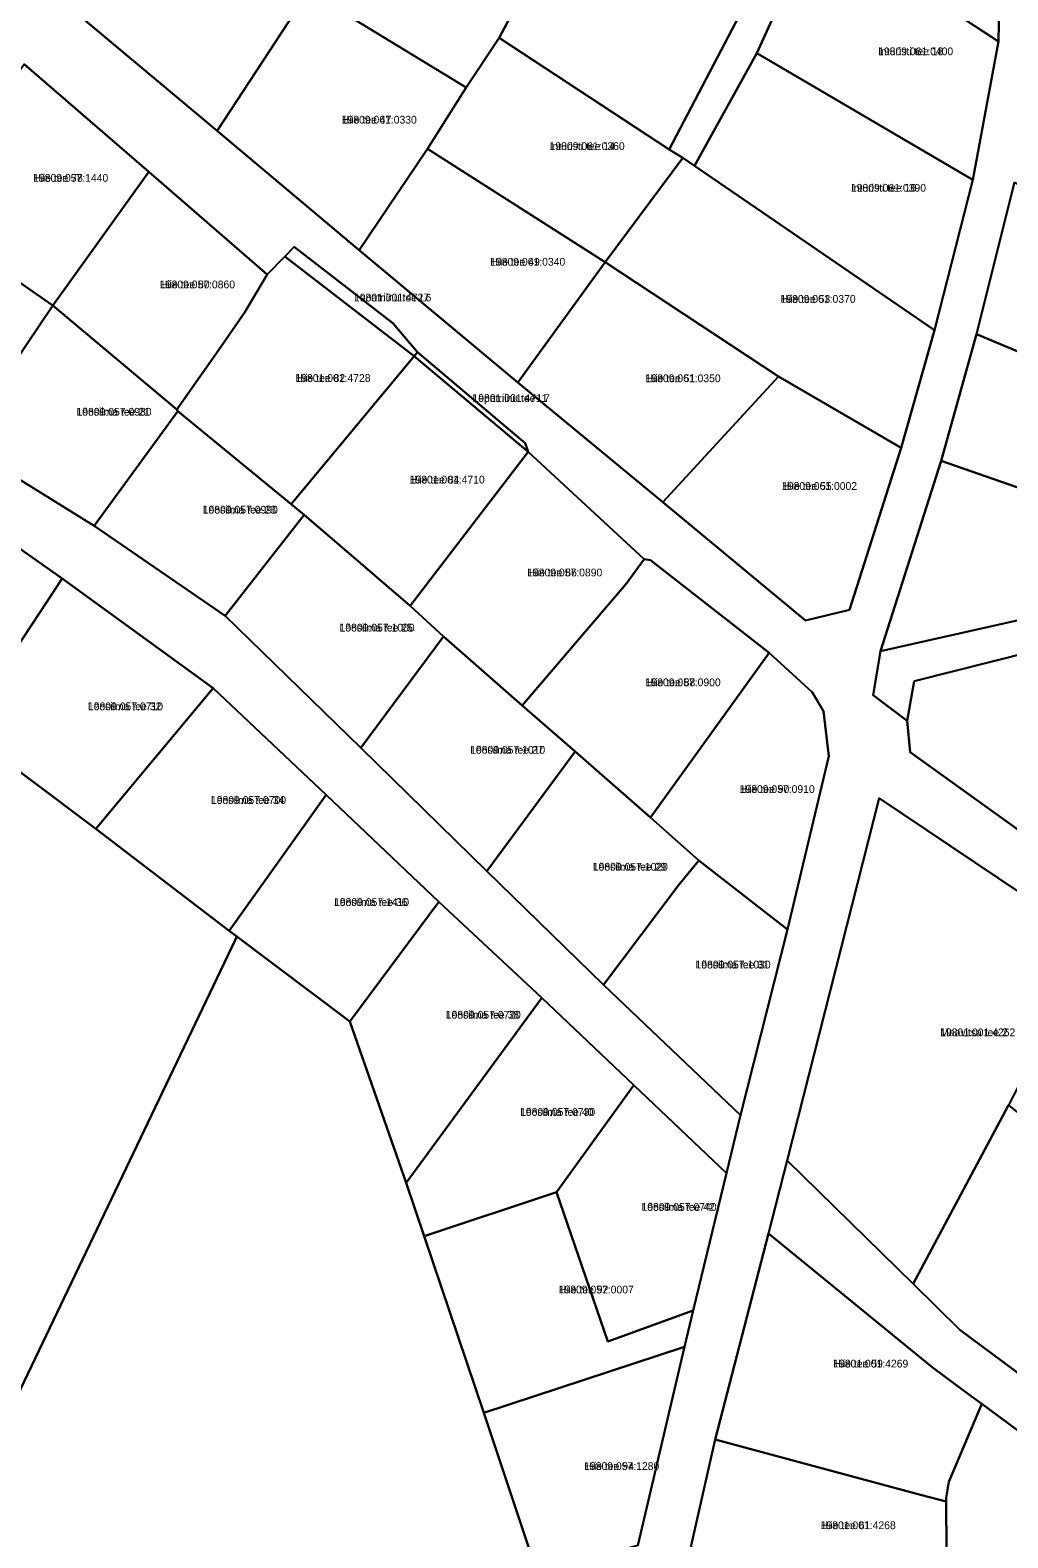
# Model space of a CAD drawing. Extents: x 516875 to 535633, y 6574491 to 6593094.
# Drawn here: x 522140.5 to 522329.4, y 6587201.6 to 6587492.9 of the extents above; entities that cross this region are included whole.
import ezdxf

# ---------------------------------------------------------------- set-up
doc = ezdxf.new("R2010")
doc.units = 0
for name, color, linetype in [('L_AADRESS', 7, 'Continuous'), ('PIIR', 7, 'Continuous'), ('TUNNUS', 7, 'Continuous')]:
    doc.layers.add(name, color=color, linetype=linetype)

msp = doc.modelspace()

# ---------------------------------------------------------------- linework, layer by layer
at = {"layer": 'PIIR'}
for points in [[(522130.99, 6587511.59), (522148.76, 6587496.75), (522176.64, 6587473.46), (522204.05, 6587450.37), (522234.69, 6587424.83), (522262.73, 6587401.7), (522290.24, 6587378.83), (522298.74, 6587380.89), (522308.74, 6587412.2), (522315.2, 6587434.91), (522322.58, 6587463.94), (522327.53, 6587490.67), (522327.74, 6587501.22), (522336.67, 6587532.97), (522349.11, 6587575.14), (522323.48, 6587593.16), (522303.51, 6587607.38), (522280.12, 6587625.51), (522255.95, 6587641.89), (522232.81, 6587658.84), (522211.04, 6587675.41), (522190.18, 6587691.24), (522170.33, 6587706.74), (522137.56, 6587733.11)], [(522291.63, 6587512.13), (522280.86, 6587488.44), (522268.8, 6587466.65), (522266.59, 6587468.22), (522263.91, 6587469.85), (522284.58, 6587509.35)], [(522327.74, 6587501.22), (522327.53, 6587490.67), (522295.68, 6587511.57)], [(522257.9, 6587200.12), (522266.88, 6587238.51), (522268.58, 6587245.55), (522275, 6587272.07), (522277.69, 6587283.26), (522286.81, 6587319.14), (522294.76, 6587352.61), (522293.75, 6587361.34), (522291.58, 6587364.97), (522283.22, 6587372.57), (522260.3, 6587390.51), (522259.13, 6587390.71), (522236.72, 6587411.45), (522236.12, 6587413.08), (522215.32, 6587430.67), (522210.59, 6587436.27), (522191.52, 6587451.05), (522189.67, 6587449.18), (522186.26, 6587445.71), (522163.43, 6587465.52), (522139.37, 6587486.34)], [(522330.66, 6587463.51), (522323.28, 6587434.15), (522316.46, 6587409.68), (522304.78, 6587372.9), (522303.37, 6587364.42), (522309.93, 6587359.42), (522310.5, 6587353.43), (522345.95, 6587327.88)], [(522126.96, 6587413.14), (522152.9, 6587397.13), (522178.19, 6587379.72), (522204.4, 6587354.21), (522228.72, 6587330.44), (522251.25, 6587308.48), (522277.69, 6587283.26), (522275, 6587272.07), (522257.13, 6587289.06), (522239.31, 6587305.92), (522219.44, 6587324.5), (522197.69, 6587345.18), (522175.86, 6587365.75), (522146.69, 6587386.92), (522120.03, 6587405.7)], [(522333.74, 6587372.78), (522311.25, 6587367.11), (522309.93, 6587359.42), (522303.37, 6587364.42), (522304.78, 6587372.9), (522332, 6587379)], [(522345.86, 6587316.74), (522304.47, 6587344.54), (522286.72, 6587274.54), (522283.12, 6587260.43), (522272.83, 6587220.63), (522268.21, 6587200.15)], [(522358.65, 6587201.13), (522335.3, 6587219.37), (522327.57, 6587225.1), (522324.3, 6587227.5), (522322.3, 6587229), (522314.73, 6587234.58), (522283.12, 6587260.43), (522286.72, 6587274.54), (522311.09, 6587250.66), (522320.1, 6587241.82), (522330.58, 6587234.01), (522347.44, 6587220.78), (522356.18, 6587214.07), (522375.8, 6587198.81)]]:
    msp.add_lwpolyline(points, dxfattribs=at)
for points in [[(522231.08, 6587491.41), (522224.74, 6587481.79), (522194.26, 6587500.4), (522211.52, 6587527.95), (522223.62, 6587525.51), (522245.69, 6587518.92)], [(522176.64, 6587473.46), (522148.76, 6587496.75), (522164.77, 6587519.53), (522194.26, 6587500.4)], [(522263.91, 6587469.85), (522231.08, 6587491.41), (522245.69, 6587518.92), (522284.58, 6587509.35)], [(522322.58, 6587463.94), (522280.86, 6587488.44), (522291.63, 6587512.13), (522295.68, 6587511.57), (522327.53, 6587490.67)], [(522217.24, 6587469.94), (522204.05, 6587450.37), (522176.64, 6587473.46), (522194.26, 6587500.4), (522224.74, 6587481.79)], [(522251.58, 6587448.05), (522217.24, 6587469.94), (522224.74, 6587481.79), (522231.08, 6587491.41), (522263.91, 6587469.85), (522266.59, 6587468.22)], [(522315.2, 6587434.91), (522268.8, 6587466.65), (522280.86, 6587488.44), (522322.58, 6587463.94)], [(522118.75, 6587457.97), (522139.37, 6587486.34), (522163.43, 6587465.52), (522144.9, 6587439.69), (522119.54, 6587457.3)], [(522234.69, 6587424.83), (522204.05, 6587450.37), (522217.24, 6587469.94), (522251.58, 6587448.05)], [(522308.74, 6587412.2), (522285.04, 6587425.96), (522251.58, 6587448.05), (522266.59, 6587468.22), (522268.8, 6587466.65), (522315.2, 6587434.91)], [(522163.43, 6587465.52), (522186.26, 6587445.71), (522181.95, 6587438.38), (522177.06, 6587431.35), (522168.85, 6587419.63), (522144.9, 6587439.69)], [(522330.66, 6587463.51), (522367.38, 6587436.69), (522363.22, 6587425.93), (522361.09, 6587418.34), (522323.28, 6587434.15)], [(522119.54, 6587457.3), (522144.9, 6587439.69), (522126.96, 6587413.14), (522102.56, 6587430.43)], [(522189.67, 6587449.18), (522191.52, 6587451.05), (522210.59, 6587436.27), (522215.32, 6587430.67), (522214.65, 6587429.9)], [(522186.26, 6587445.71), (522189.67, 6587449.18), (522214.65, 6587429.9), (522190.91, 6587401.28), (522169.02, 6587419.25), (522168.85, 6587419.63), (522177.06, 6587431.35), (522181.95, 6587438.38)], [(522262.73, 6587401.7), (522234.69, 6587424.83), (522251.58, 6587448.05), (522285.04, 6587425.96)], [(522144.9, 6587439.69), (522168.85, 6587419.63), (522169.02, 6587419.25), (522152.9, 6587397.13), (522126.96, 6587413.14)], [(522323.28, 6587434.15), (522361.09, 6587418.34), (522355.52, 6587396.09), (522316.46, 6587409.68)], [(522214.65, 6587429.9), (522215.32, 6587430.67), (522236.12, 6587413.08), (522236.72, 6587411.45)], [(522190.91, 6587401.28), (522214.65, 6587429.9), (522236.72, 6587411.45), (522213.89, 6587381.65), (522193.41, 6587399.22)], [(522308.74, 6587412.2), (522298.74, 6587380.89), (522290.24, 6587378.83), (522262.73, 6587401.7), (522285.04, 6587425.96)], [(522169.02, 6587419.25), (522190.91, 6587401.28), (522193.41, 6587399.22), (522178.19, 6587379.72), (522152.9, 6587397.13)], [(522220.32, 6587375.75), (522213.89, 6587381.65), (522236.72, 6587411.45), (522259.13, 6587390.71), (522255.64, 6587385.92), (522235.57, 6587362.44)], [(522316.46, 6587409.68), (522355.52, 6587396.09), (522350.49, 6587380.66), (522332, 6587379), (522304.78, 6587372.9)], [(522120.03, 6587405.7), (522146.69, 6587386.92), (522127.48, 6587357.83), (522099.49, 6587379.1)], [(522193.41, 6587399.22), (522213.89, 6587381.65), (522220.32, 6587375.75), (522204.4, 6587354.21), (522178.19, 6587379.72)], [(522235.57, 6587362.44), (522255.64, 6587385.92), (522259.13, 6587390.71), (522260.3, 6587390.51), (522283.22, 6587372.57), (522260.34, 6587340.79), (522245.76, 6587353.54)], [(522146.69, 6587386.92), (522175.86, 6587365.75), (522153.17, 6587338.57), (522127.48, 6587357.83)], [(522220.32, 6587375.75), (522235.57, 6587362.44), (522245.76, 6587353.54), (522228.72, 6587330.44), (522204.4, 6587354.21)], [(522309.93, 6587359.42), (522311.25, 6587367.11), (522333.74, 6587372.78), (522364.67, 6587374.82), (522345.95, 6587327.88), (522310.5, 6587353.43)], [(522260.34, 6587340.79), (522283.22, 6587372.57), (522291.58, 6587364.97), (522293.75, 6587361.34), (522294.76, 6587352.61), (522286.81, 6587319.14), (522269.66, 6587332.48)], [(522175.86, 6587365.75), (522197.69, 6587345.18), (522178.96, 6587318.86), (522153.17, 6587338.57)], [(522037.89, 6587203.55), (522127.48, 6587357.83), (522153.17, 6587338.57), (522178.96, 6587318.86), (522180.41, 6587317.76), (522180.09, 6587317.1), (522022.74, 6586987.98), (522018.35, 6586991.01), (521975.04, 6587020.48), (521949.53, 6587051.29)], [(522245.76, 6587353.54), (522260.34, 6587340.79), (522269.66, 6587332.48), (522265.82, 6587327.77), (522251.25, 6587308.48), (522228.72, 6587330.44)], [(522197.69, 6587345.18), (522219.44, 6587324.5), (522202.26, 6587301.34), (522180.41, 6587317.76), (522178.96, 6587318.86)], [(522286.72, 6587274.54), (522304.47, 6587344.54), (522345.86, 6587316.74), (522329.47, 6587285.22), (522311.09, 6587250.66)], [(522265.82, 6587327.77), (522269.66, 6587332.48), (522286.81, 6587319.14), (522277.69, 6587283.26), (522251.25, 6587308.48)], [(522202.26, 6587301.34), (522219.44, 6587324.5), (522239.31, 6587305.92), (522213.15, 6587270.17)], [(522180.41, 6587317.76), (522202.26, 6587301.34), (522213.15, 6587270.17), (522216.62, 6587259.92), (522228.15, 6587225.78), (522238.46, 6587194.82), (522239.47, 6587190.75), (522248.99, 6587139.07), (522253.11, 6587122.8), (522269.02, 6587069.13), (522287.25, 6587072.93), (522290.17, 6587041.41), (522252.33, 6587025.14), (522228.77, 6587015.49), (522186.71, 6586997.23), (522138.92, 6586976.48), (522090.68, 6586955.54), (522064.45, 6586965.46), (522062.93, 6586963.36), (522022.74, 6586987.98), (522180.09, 6587317.1)], [(522213.15, 6587270.17), (522239.31, 6587305.92), (522257.13, 6587289.06), (522242.17, 6587268.38), (522216.62, 6587259.92)], [(522242.17, 6587268.38), (522257.13, 6587289.06), (522275, 6587272.07), (522268.58, 6587245.55), (522252.12, 6587239.55)], [(522311.09, 6587250.66), (522329.47, 6587285.22), (522350.04, 6587268.61), (522364.58, 6587256.8), (522347.44, 6587220.78), (522330.58, 6587234.01), (522320.1, 6587241.82)], [(522242.17, 6587268.38), (522252.12, 6587239.55), (522268.58, 6587245.55), (522266.88, 6587238.51), (522228.15, 6587225.78), (522216.62, 6587259.92)], [(522272.83, 6587220.63), (522283.12, 6587260.43), (522314.73, 6587234.58), (522322.3, 6587229), (522324.3, 6587227.5), (522317.94, 6587212.42), (522317.46, 6587209.31), (522317.46, 6587208.6), (522312.48, 6587209.94)], [(522228.15, 6587225.78), (522266.88, 6587238.51), (522257.9, 6587200.12), (522238.46, 6587194.82)], [(522317.94, 6587212.42), (522324.3, 6587227.5), (522327.57, 6587225.1), (522335.3, 6587219.37), (522358.65, 6587201.13), (522344.06, 6587162.19), (522339.87, 6587150.8), (522331.19, 6587155.64), (522330.78, 6587160.26), (522325.97, 6587172.03), (522322.75, 6587179.8), (522320.8, 6587185.64), (522319.38, 6587192.1), (522319.44, 6587194.66), (522319.35, 6587195.32), (522319.15, 6587196.84), (522317.49, 6587199.44), (522317.46, 6587208.6), (522317.46, 6587209.31)], [(522268.21, 6587200.15), (522272.83, 6587220.63), (522312.48, 6587209.94), (522317.46, 6587208.6), (522317.49, 6587199.44), (522319.15, 6587196.84), (522319.35, 6587195.32), (522310.78, 6587193.64), (522271.58, 6587185.94)]]:
    msp.add_lwpolyline(points, close=True, dxfattribs=at)

# ---------------------------------------------------------------- texts
at = {"layer": 'L_AADRESS'}
for s, p in [('Inturisti tee 18', (522304.3, 6587488.04)), ('Hiie tee 47', (522200.69, 6587474.84)), ('Inturisti tee 14', (522240.84, 6587469.73)), ('Hiie tee 78', (522141.09, 6587463.59)), ('Inturisti tee 16', (522299.04, 6587461.68)), ('Hiie tee 49', (522229.36, 6587447.38)), ('Hiie tee 80', (522165.58, 6587443.01)), ('Lepatriinu tee L6', (522203.06, 6587440.48)), ('Hiie tee 53', (522285.45, 6587440.21)), ('Hiie tee 82', (522191.75, 6587424.93)), ('Hiie tee 51', (522259.38, 6587424.88)), ('Lepatriinu tee L7', (522225.95, 6587421.06)), ('Lõosilma tee 21', (522149.46, 6587418.41)), ('Hiie tee 84', (522213.81, 6587405.3)), ('Hiie tee 55', (522285.73, 6587404.07)), ('Lõosilma tee 23', (522173.85, 6587399.49)), ('Hiie tee 86', (522236.51, 6587387.36)), ('Lõosilma tee 25', (522200.27, 6587376.71)), ('Hiie tee 88', (522259.39, 6587366.14)), ('Lõosilma tee 32', (522151.67, 6587361.5)), ('Lõosilma tee 27', (522225.49, 6587353.1)), ('Hiie tee 90', (522277.55, 6587345.52)), ('Lõosilma tee 34', (522175.43, 6587343.4)), ('Lõosilma tee 29', (522249.19, 6587330.51)), ('Lõosilma tee 36', (522199.2, 6587323.69)), ('Lõosilma tee 31', (522269.03, 6587311.61)), ('Lõosilma tee 38', (522220.79, 6587301.92)), ('Maavitsa tee 2', (522316.29, 6587298.52)), ('Lõosilma tee 40', (522235.14, 6587283.14)), ('Lõosilma tee 42', (522258.59, 6587264.79)), ('Hiie tee 92', (522242.6, 6587248.83)), ('Hiie tee 59', (522295.62, 6587234.52)), ('Hiie tee 94', (522247.52, 6587214.72)), ('Hiie tee 61', (522293.2, 6587203.29))]:
    msp.add_text(s, height=1.5, dxfattribs=at).set_placement(p)
at = {"layer": 'TUNNUS'}
for s, p in [('19809:061:0400', (522304.3, 6587488.04)), ('19809:061:0330', (522200.69, 6587474.84)), ('19809:061:0360', (522240.84, 6587469.73)), ('19809:057:1440', (522141.09, 6587463.59)), ('19809:061:0390', (522299.04, 6587461.68)), ('19809:061:0340', (522229.36, 6587447.38)), ('19809:057:0860', (522165.58, 6587443.01)), ('19801:001:4727', (522203.06, 6587440.48)), ('19809:061:0370', (522285.45, 6587440.21)), ('19801:001:4728', (522191.75, 6587424.93)), ('19809:061:0350', (522259.38, 6587424.88)), ('19801:001:4711', (522225.95, 6587421.06)), ('19809:057:0980', (522149.46, 6587418.41)), ('19801:001:4710', (522213.81, 6587405.3)), ('19809:061:0002', (522285.73, 6587404.07)), ('19809:057:0990', (522173.85, 6587399.49)), ('19809:057:0890', (522236.51, 6587387.36)), ('19809:057:1000', (522200.27, 6587376.71)), ('19809:057:0900', (522259.39, 6587366.14)), ('19809:057:0710', (522151.67, 6587361.5)), ('19809:057:1010', (522225.49, 6587353.1)), ('19809:057:0910', (522277.55, 6587345.52)), ('19809:057:0700', (522175.43, 6587343.4)), ('19809:057:1020', (522249.19, 6587330.51)), ('19809:057:1410', (522199.2, 6587323.69)), ('19809:057:1030', (522269.03, 6587311.61)), ('19809:057:0720', (522220.79, 6587301.92)), ('19801:001:4262', (522316.29, 6587298.52)), ('19809:057:0730', (522235.14, 6587283.14)), ('19809:057:0740', (522258.59, 6587264.79)), ('19809:057:0007', (522242.6, 6587248.83)), ('19801:001:4269', (522295.62, 6587234.52)), ('19809:057:1280', (522247.52, 6587214.72)), ('19801:001:4268', (522293.2, 6587203.29))]:
    msp.add_text(s, height=1.5, dxfattribs=at).set_placement(p)

doc.saveas('drawing.dxf')
